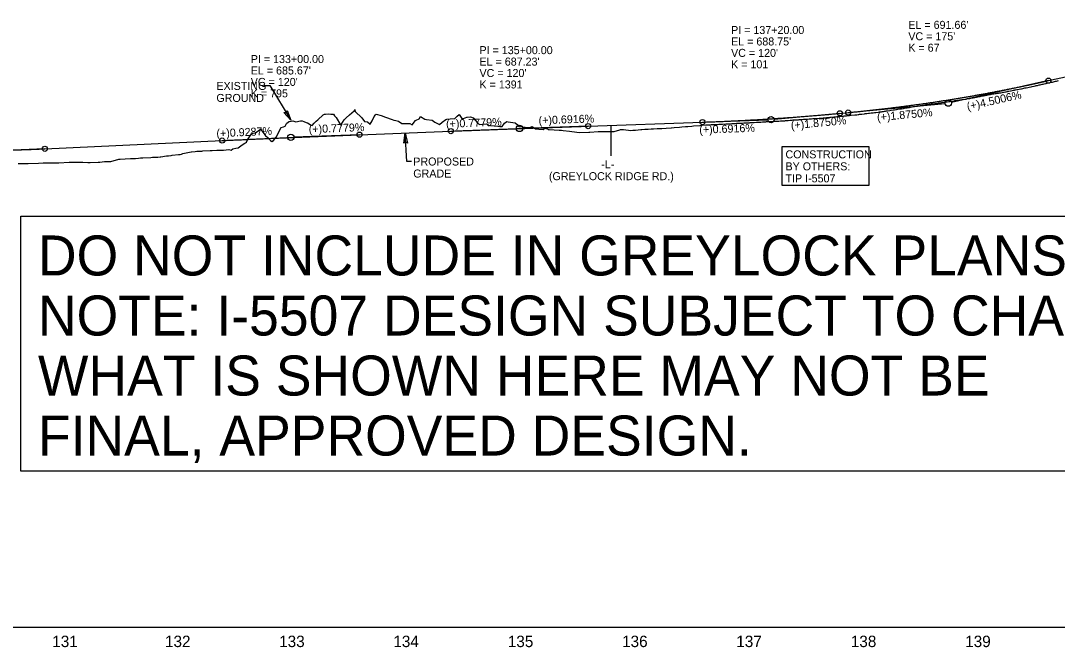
# Model space of a CAD drawing. Extents: x 1518255 to 1527303, y 471773 to 504546.
# Drawn here: x 1520134 to 1521041, y 497627 to 498175 of the extents above; entities that cross this region are included whole.
import ezdxf

# ---------------------------------------------------------------- set-up
doc = ezdxf.new("R2010")
doc.units = 0
for name, color, linetype in [('Exist Profile Cell', 7, 'Continuous'), ('Exist Vertical Profile Ground Line', 7, 'Continuous'), ('Exist Vertical Profile Horizontal Axis Label Major', 7, 'Continuous'), ('Prop Dimension', 7, 'Continuous'), ('Prop Dimension Text', 7, 'Continuous'), ('Prop Grid Mask', 7, 'Continuous'), ('Prop Terminator CELL', 7, 'Continuous'), ('Prop Vertical Profile Curve Label', 7, 'Continuous'), ('Prop Vertical Profile Grade Label', 7, 'Continuous'), ('Prop VPI Label', 7, 'Continuous')]:
    doc.layers.add(name, color=color, linetype=linetype)

msp = doc.modelspace()

# ---------------------------------------------------------------- linework, layer by layer
at = {"layer": 'Exist Profile Cell'}
msp.add_line((1519570.42, 497645.02), (1521670.42, 497645.02), dxfattribs=at)
at = {"layer": 'Exist Vertical Profile Ground Line'}
msp.add_lwpolyline([(1520131.92, 498050.38), (1520136.35, 498050.4), (1520140.85, 498050.54), (1520149.78, 498050.84), (1520154, 498050.98), (1520158.71, 498050.99), (1520166.47, 498051.02), (1520167.63, 498051.09), (1520176.56, 498051.57), (1520177.57, 498051.63), (1520185.49, 498051.74), (1520188.53, 498051.78), (1520193, 498051.39), (1520194.42, 498051.37), (1520195.1, 498051.37), (1520201.99, 498051.67), (1520203.35, 498051.8), (1520207.39, 498052.19), (1520209.6, 498052.23), (1520212.28, 498052.18), (1520213.14, 498052.16), (1520220.06, 498054.32), (1520221.21, 498054.39), (1520225.58, 498054.66), (1520230.14, 498054.82), (1520234.76, 498054.97), (1520237.26, 498055.15), (1520239.07, 498055.34), (1520241.09, 498055.57), (1520248, 498055.87), (1520249.39, 498055.95), (1520251.87, 498056.06), (1520254.14, 498056.02), (1520256.24, 498056.36), (1520256.92, 498056.45), (1520261.76, 498057.08), (1520263.47, 498057.3), (1520265.85, 498057.62), (1520266.78, 498057.75), (1520272.34, 498058.36), (1520273.79, 498058.36), (1520274.78, 498058.78), (1520276.1, 498059.35), (1520283.32, 498060.75), (1520283.71, 498060.78), (1520286.76, 498061.01), (1520288.2, 498061.35), (1520292.64, 498061.44), (1520293.38, 498061.46), (1520299.89, 498061.77), (1520301.57, 498061.88), (1520305.78, 498062.18), (1520310.5, 498062.25), (1520311.59, 498062.27), (1520316.16, 498062.67), (1520318.25, 498062.24), (1520319.68, 498063.48), (1520322.34, 498063.85), (1520324.53, 498064.18), (1520328.02, 498066.96), (1520328.36, 498067.19), (1520329.72, 498068.1), (1520330.94, 498068.71), (1520331.6, 498069.28), (1520332.56, 498071.3), (1520334.88, 498074.65), (1520336.22, 498076.55), (1520337.29, 498076.95), (1520337.66, 498077.09), (1520339.48, 498077.36), (1520343.18, 498080.08), (1520343.91, 498080.51), (1520344.26, 498080.39), (1520346.21, 498077.76), (1520348.38, 498074.83), (1520350.1, 498073.41), (1520352.61, 498070.61), (1520353.95, 498069.73), (1520355.3, 498070.65), (1520357.68, 498073.64), (1520361.94, 498082.03), (1520364.07, 498082.72), (1520365.65, 498083.23), (1520366.66, 498085.4), (1520368.47, 498087.11), (1520368.88, 498087.21), (1520369.32, 498087.35), (1520372.28, 498087.85), (1520373, 498087.63), (1520374.92, 498087.04), (1520379.01, 498087.91), (1520380.32, 498087.7), (1520381.93, 498087.29), (1520383.91, 498086.46), (1520385.01, 498086.12), (1520388.33, 498083.94), (1520389.13, 498083.76), (1520390.86, 498085.7), (1520392.53, 498087.59), (1520393.94, 498088.84), (1520398.87, 498093.09), (1520399.96, 498093.69), (1520400.78, 498093.73), (1520403.82, 498093.94), (1520405.52, 498093.75), (1520407.72, 498093.72), (1520408.72, 498092.35), (1520409.39, 498091.42), (1520410.21, 498090.9), (1520413.94, 498084.35), (1520414.33, 498084.1), (1520417.18, 498088.8), (1520417.65, 498089.26), (1520418.9, 498090.51), (1520421.72, 498093.22), (1520425.74, 498096.6), (1520426.29, 498097.61), (1520426.68, 498095.96), (1520432.64, 498090.53), (1520434.98, 498087.26), (1520435.5, 498087.2), (1520437.41, 498086.97), (1520439.91, 498084.92), (1520441.55, 498087.83), (1520443.34, 498091.66), (1520444.43, 498092.95), (1520444.96, 498093.57), (1520449.36, 498092.47), (1520453.36, 498091.07), (1520459.22, 498089), (1520460.65, 498088.34), (1520462.29, 498087.99), (1520464.48, 498087.52), (1520467.67, 498085.44), (1520469.07, 498085.45), (1520471.22, 498085.45), (1520474.4, 498085.44), (1520476.63, 498084.32), (1520479.55, 498088.1), (1520480.15, 498088.38), (1520482.67, 498089.54), (1520483.76, 498091.75), (1520487.61, 498089.26), (1520489.22, 498089), (1520494.04, 498088.31), (1520496.49, 498086.72), (1520498.01, 498085.87), (1520500.35, 498084.57), (1520502.82, 498086.76), (1520506.07, 498089.15), (1520506.94, 498089.26), (1520509.81, 498089.6), (1520513.99, 498089.95), (1520515.86, 498091.78), (1520517.61, 498093.47), (1520519.88, 498089.93), (1520521.53, 498089.9), (1520524.27, 498091.12), (1520524.79, 498091.16), (1520527.58, 498091.34), (1520529.95, 498090.46), (1520533.72, 498086.17), (1520534.48, 498085.31), (1520535.11, 498085.06), (1520535.42, 498084.57), (1520541.61, 498085.29), (1520542.65, 498084.53), (1520543.41, 498083.97), (1520544.95, 498083.88), (1520551.58, 498083.09), (1520553.29, 498082.88), (1520555.17, 498082.83), (1520557.36, 498085.67), (1520559.34, 498087.25), (1520560.51, 498087.08), (1520566.68, 498086.11), (1520568.47, 498084.68), (1520569.71, 498082.76), (1520578.37, 498082.05), (1520579.76, 498081.93), (1520580.68, 498082.56), (1520581.57, 498082.8), (1520584.45, 498080.75), (1520587.3, 498080.57), (1520591.09, 498080.31), (1520592.8, 498081.58), (1520593.87, 498081.23), (1520594.5, 498081.07), (1520595.49, 498080.26), (1520596.23, 498080.21), (1520605.15, 498079.68), (1520607.16, 498079.55), (1520608.62, 498079.47), (1520614.08, 498078.84), (1520620.46, 498078.01), (1520622.81, 498077.62), (1520631.13, 498077.99), (1520631.94, 498078.04), (1520639.24, 498078.52), (1520640.87, 498078.62), (1520641.19, 498078.64), (1520646.97, 498078.41), (1520649.8, 498078.39), (1520651.29, 498078.38), (1520653.29, 498078.53), (1520658.28, 498080.11), (1520658.73, 498080.14), (1520661.37, 498080.29), (1520667.68, 498079.44), (1520669.56, 498079.57), (1520671.72, 498079.71), (1520676.59, 498080.17), (1520677.32, 498080.24), (1520679.93, 498080.41), (1520682.94, 498080.61), (1520685.52, 498080.73), (1520687.55, 498080.82), (1520690.86, 498081.07), (1520694.44, 498081.15), (1520694.81, 498081.16), (1520698.61, 498081.47), (1520702.92, 498081.83), (1520703.37, 498081.85), (1520705.74, 498081.97), (1520710.35, 498082.36), (1520712.3, 498082.52), (1520715.46, 498082.78), (1520717.51, 498082.96), (1520721.23, 498083.26), (1520722.69, 498083.37), (1520728.09, 498083.81), (1520728.57, 498083.83), (1520730.16, 498083.97), (1520733.25, 498084.25), (1520736.75, 498084.41), (1520738.03, 498084.49), (1520738.35, 498084.51), (1520742.17, 498084.68), (1520743.63, 498084.75), (1520744.7, 498084.85), (1520745.9, 498084.9), (1520746.29, 498084.92), (1520747.79, 498085), (1520750.79, 498085.19), (1520751.77, 498085.23), (1520752.4, 498085.24), (1520752.84, 498085.26), (1520753.78, 498085.32), (1520756.04, 498085.45), (1520757.78, 498085.52), (1520758.91, 498085.61), (1520760.15, 498085.67), (1520761.33, 498085.7), (1520761.65, 498085.72), (1520762.15, 498085.75), (1520764.37, 498085.88), (1520764.9, 498085.91), (1520765.29, 498085.92), (1520766.73, 498085.96), (1520768.66, 498086.1), (1520769.52, 498086.14), (1520771.41, 498086.21), (1520772.07, 498086.24), (1520772.92, 498086.31), (1520773.86, 498086.37), (1520774.53, 498086.38), (1520775.66, 498086.39), (1520777.62, 498086.53), (1520778.65, 498086.59), (1520780.68, 498086.7), (1520781.02, 498086.71), (1520781.48, 498086.76), (1520782.81, 498086.88), (1520783.76, 498086.9), (1520784.6, 498086.92), (1520785.26, 498086.99), (1520785.75, 498087.04), (1520786.4, 498087.12), (1520786.86, 498087.12), (1520790.03, 498087.27), (1520793.14, 498087.46), (1520793.56, 498087.46), (1520794.35, 498087.53), (1520795.34, 498087.63), (1520796.07, 498087.63), (1520797.15, 498087.67), (1520798.63, 498087.74), (1520799.16, 498087.78), (1520800.49, 498087.84), (1520801.01, 498087.88), (1520802.52, 498087.95), (1520802.92, 498088), (1520805.29, 498088.23), (1520807.23, 498088.34), (1520807.89, 498088.39), (1520808.36, 498088.43), (1520808.88, 498088.49), (1520809.68, 498088.59), (1520811.53, 498088.61), (1520813.28, 498088.8), (1520814.53, 498088.85), (1520815.08, 498088.88), (1520815.84, 498088.91), (1520816.75, 498088.99), (1520817.57, 498089.06), (1520818.65, 498089.2), (1520820.64, 498089.23), (1520822.23, 498089.43), (1520823.71, 498089.52), (1520824.03, 498089.54), (1520824.63, 498089.57), (1520825.83, 498089.65), (1520826.8, 498089.77), (1520827.63, 498089.88), (1520828.79, 498089.91), (1520829.87, 498089.98), (1520832.5, 498090.16), (1520833.1, 498090.21), (1520834.78, 498090.29), (1520835.97, 498090.42), (1520836.58, 498090.49), (1520837.44, 498090.53), (1520838.39, 498090.56), (1520839.07, 498090.66), (1520840.37, 498090.78), (1520841.74, 498090.92), (1520842.1, 498090.95), (1520842.96, 498091.04), (1520845.15, 498091.24), (1520845.53, 498091.3), (1520846.08, 498091.32), (1520847.34, 498091.34), (1520848.24, 498091.5), (1520849.15, 498091.62), (1520850.42, 498091.74), (1520851.3, 498091.8), (1520853.36, 498092.03), (1520854.33, 498092.12), (1520854.75, 498092.16), (1520856.3, 498092.24), (1520857.4, 498092.4), (1520858.1, 498092.47), (1520859.1, 498092.6), (1520859.91, 498092.66), (1520860.48, 498092.73), (1520863.5, 498093.06), (1520863.99, 498093.09), (1520865.27, 498093.17), (1520866.57, 498093.37), (1520867.08, 498093.43), (1520867.8, 498093.53), (1520868.88, 498093.61), (1520869.64, 498093.71), (1520872.13, 498094.05), (1520872.69, 498094.12), (1520874.25, 498094.22), (1520875.72, 498094.49), (1520876.04, 498094.53), (1520876.5, 498094.6), (1520877.85, 498094.75), (1520878.82, 498094.86), (1520879.73, 498094.92), (1520880.83, 498095.12), (1520881.88, 498095.25), (1520884.21, 498095.53), (1520885.2, 498095.65), (1520886.83, 498095.84), (1520887.6, 498095.93), (1520887.96, 498095.98), (1520888.62, 498096.02), (1520889.56, 498096.23), (1520890.4, 498096.39), (1520890.99, 498096.45), (1520892.2, 498096.58), (1520894.34, 498096.92), (1520895.47, 498097.09), (1520897.08, 498097.34), (1520898.29, 498097.55), (1520899.38, 498097.76), (1520900.14, 498097.84), (1520901.2, 498097.96), (1520902.7, 498098.22), (1520903.35, 498098.32), (1520904.4, 498098.48), (1520906.23, 498098.77), (1520906.56, 498098.81), (1520907.06, 498098.9), (1520908.38, 498099.16), (1520909.29, 498099.25), (1520911.41, 498099.59), (1520911.93, 498099.69), (1520912.3, 498099.74), (1520913.75, 498099.97), (1520915.84, 498100.28), (1520918.41, 498100.72), (1520919.09, 498100.83), (1520920.2, 498101), (1520920.95, 498101.14), (1520921.46, 498101.22), (1520922.75, 498101.45), (1520924.6, 498101.67), (1520926.32, 498102.03), (1520926.96, 498102.1), (1520927.53, 498102.16), (1520928.12, 498102.24), (1520928.99, 498102.36), (1520929.93, 498102.51), (1520930.58, 498102.6), (1520931.74, 498102.77), (1520933.62, 498102.96), (1520934.13, 498103.03), (1520934.83, 498103.13), (1520936.64, 498103.4), (1520937.11, 498103.46), (1520937.79, 498103.55), (1520938.92, 498103.72), (1520939.7, 498103.83), (1520942.17, 498104.13), (1520942.71, 498104.21), (1520944.3, 498104.51), (1520945.76, 498104.68), (1520946.11, 498104.73), (1520946.61, 498104.8), (1520948.78, 498105.16), (1520950.58, 498105.43), (1520951.02, 498105.5), (1520951.8, 498105.63), (1520953.28, 498105.94), (1520955.09, 498106.21), (1520955.43, 498106.23), (1520957.11, 498106.46), (1520957.89, 498106.46), (1520958.45, 498106.52), (1520959.83, 498106.68), (1520960.38, 498106.76), (1520960.9, 498106.88), (1520962.27, 498107.23), (1520964.25, 498107.5), (1520966.32, 498107.92), (1520966.98, 498108.05), (1520968.7, 498108.35), (1520970.01, 498108.61), (1520971.29, 498108.92), (1520973.13, 498109.17), (1520974.19, 498109.41), (1520975.14, 498109.62), (1520976.06, 498109.78), (1520976.66, 498109.93), (1520977.55, 498110.04), (1520978.32, 498110.2), (1520979.11, 498110.34), (1520980.28, 498110.64), (1520982.15, 498110.92), (1520984.07, 498111.46), (1520985.12, 498111.58), (1520986.44, 498111.75), (1520987.22, 498111.81), (1520988.16, 498111.96), (1520989.27, 498112.15), (1520989.94, 498112.24), (1520991.38, 498112.45), (1520993.59, 498112.89), (1520994.18, 498113.03), (1520995.33, 498113.23), (1520995.95, 498113.32), (1520996.91, 498113.51), (1520997.24, 498113.56), (1520997.81, 498113.69), (1520998.27, 498113.79), (1520999.79, 498114.04), (1521000.09, 498114.1), (1521000.46, 498114.17), (1521002.28, 498114.53), (1521003.28, 498114.76), (1521003.65, 498114.86), (1521004.21, 498114.94), (1521005.3, 498115.12), (1521005.68, 498115.19), (1521006.31, 498115.3), (1521007.27, 498115.53), (1521008.83, 498115.83), (1521009.31, 498115.93), (1521010.49, 498116.17), (1521012.34, 498116.56), (1521012.65, 498116.65), (1521013.12, 498116.73), (1521013.55, 498116.81), (1521014.85, 498117.06), (1521016.15, 498117.33), (1521017.97, 498117.72), (1521018.64, 498117.87), (1521020.08, 498118.17), (1521020.45, 498118.24), (1521021.65, 498118.53), (1521022.07, 498118.6), (1521023.36, 498118.87), (1521024.76, 498119.19), (1521025.63, 498119.41), (1521026.63, 498119.62), (1521027.45, 498119.8), (1521028.43, 498120), (1521029.3, 498120.19), (1521030.39, 498120.44), (1521031.05, 498120.59), (1521032.92, 498121.01), (1521033.72, 498121.19), (1521034.47, 498121.38), (1521035.49, 498121.59), (1521036.45, 498121.8), (1521037.25, 498121.97), (1521039.08, 498122.39), (1521039.44, 498122.46), (1521040, 498122.58), (1521041.81, 498123)], dxfattribs=at)
at = {"layer": 'Prop Dimension'}
for p, q in [((1520347.27, 498118.69), (1520352.21, 498118.69)), ((1520352.21, 498118.69), (1520370.42, 498088.28)), ((1520471.87, 498052.15), (1520470.42, 498077.27)), ((1520476.04, 498052.15), (1520471.87, 498052.15))]:
    msp.add_line(p, q, dxfattribs=at)
at = {"layer": 'Prop Grid Mask'}
for p, q in [((1521032.92, 498122.99), (1521065.42, 498130.3)), ((1520850.42, 498094.39), (1520857.92, 498095.09)), ((1520630.42, 498083.23), (1520730.42, 498086.69)), ((1520430.42, 498075.71), (1520510.42, 498078.82)), ((1520155.42, 498063.4), (1520310.42, 498070.59))]:
    msp.add_line(p, q, dxfattribs=at)
for points in [[(1520800, 498065.41), (1520875.98, 498065.41), (1520875.98, 498031.27), (1520800, 498031.27)], [(1520134.29, 498004.57), (1521246.11, 498004.57), (1521246.11, 497781.32), (1520134.29, 497781.32)]]:
    msp.add_lwpolyline(points, close=True, dxfattribs=at)
for points in [[(1520857.92, 498095.09), (1520861.42, 498095.43), (1520864.92, 498095.77), (1520868.42, 498096.12), (1520871.92, 498096.48), (1520875.42, 498096.85), (1520878.92, 498097.23), (1520882.42, 498097.62), (1520885.92, 498098.01), (1520889.42, 498098.42), (1520892.92, 498098.83), (1520896.42, 498099.26), (1520899.92, 498099.69), (1520903.42, 498100.14), (1520906.92, 498100.59), (1520910.42, 498101.05), (1520913.92, 498101.52), (1520917.42, 498102), (1520920.92, 498102.49), (1520924.42, 498102.99), (1520927.92, 498103.49), (1520931.42, 498104.01), (1520934.92, 498104.54), (1520938.42, 498105.07), (1520941.92, 498105.62), (1520945.42, 498106.17), (1520948.92, 498106.73), (1520952.42, 498107.3), (1520955.92, 498107.88), (1520959.42, 498108.47), (1520962.92, 498109.07), (1520966.42, 498109.68), (1520969.92, 498110.3), (1520973.42, 498110.93), (1520976.92, 498111.56), (1520980.42, 498112.21), (1520983.92, 498112.86), (1520987.42, 498113.52), (1520990.92, 498114.2), (1520994.42, 498114.88), (1520997.92, 498115.57), (1521001.42, 498116.27), (1521004.92, 498116.98), (1521008.42, 498117.7), (1521011.92, 498118.43), (1521015.42, 498119.16), (1521018.92, 498119.91), (1521022.42, 498120.67), (1521025.92, 498121.43), (1521029.42, 498122.2), (1521032.92, 498122.99)], [(1520730.42, 498086.69), (1520732.82, 498086.78), (1520735.22, 498086.86), (1520737.62, 498086.95), (1520740.02, 498087.05), (1520742.42, 498087.14), (1520744.82, 498087.24), (1520747.22, 498087.34), (1520749.62, 498087.45), (1520752.02, 498087.55), (1520754.42, 498087.66), (1520756.82, 498087.78), (1520759.22, 498087.89), (1520761.62, 498088.01), (1520764.02, 498088.13), (1520766.42, 498088.26), (1520768.82, 498088.38), (1520771.22, 498088.51), (1520773.62, 498088.65), (1520776.02, 498088.78), (1520778.42, 498088.92), (1520780.82, 498089.06), (1520783.22, 498089.2), (1520785.62, 498089.35), (1520788.02, 498089.5), (1520790.42, 498089.65), (1520792.82, 498089.81), (1520795.22, 498089.97), (1520797.62, 498090.13), (1520800.02, 498090.29), (1520802.42, 498090.46), (1520804.82, 498090.63), (1520807.22, 498090.8), (1520809.62, 498090.98), (1520812.02, 498091.15), (1520814.42, 498091.34), (1520816.82, 498091.52), (1520819.22, 498091.71), (1520821.62, 498091.9), (1520824.02, 498092.09), (1520826.42, 498092.28), (1520828.82, 498092.48), (1520831.22, 498092.68), (1520833.62, 498092.89), (1520836.02, 498093.09), (1520838.42, 498093.3), (1520840.82, 498093.51), (1520843.22, 498093.73), (1520845.62, 498093.95), (1520848.02, 498094.17), (1520850.42, 498094.39)], [(1520510.42, 498078.82), (1520512.82, 498078.92), (1520515.22, 498079.01), (1520517.62, 498079.1), (1520520.02, 498079.2), (1520522.42, 498079.29), (1520524.82, 498079.38), (1520527.22, 498079.47), (1520529.62, 498079.56), (1520532.02, 498079.66), (1520534.42, 498079.75), (1520536.82, 498079.84), (1520539.22, 498079.93), (1520541.62, 498080.02), (1520544.02, 498080.11), (1520546.42, 498080.2), (1520548.82, 498080.29), (1520551.22, 498080.38), (1520553.62, 498080.47), (1520556.02, 498080.56), (1520558.42, 498080.65), (1520560.82, 498080.74), (1520563.22, 498080.83), (1520565.62, 498080.92), (1520568.02, 498081.01), (1520570.42, 498081.09), (1520572.82, 498081.18), (1520575.22, 498081.27), (1520577.62, 498081.36), (1520580.02, 498081.44), (1520582.42, 498081.53), (1520584.82, 498081.62), (1520587.22, 498081.71), (1520589.62, 498081.79), (1520592.02, 498081.88), (1520594.42, 498081.96), (1520596.82, 498082.05), (1520599.22, 498082.14), (1520601.62, 498082.22), (1520604.02, 498082.31), (1520606.42, 498082.39), (1520608.82, 498082.48), (1520611.22, 498082.56), (1520613.62, 498082.65), (1520616.02, 498082.73), (1520618.42, 498082.82), (1520620.82, 498082.9), (1520623.22, 498082.98), (1520625.62, 498083.07), (1520628.02, 498083.15), (1520630.42, 498083.23)], [(1520310.42, 498070.59), (1520312.82, 498070.7), (1520315.22, 498070.82), (1520317.62, 498070.93), (1520320.02, 498071.04), (1520322.42, 498071.15), (1520324.82, 498071.26), (1520327.22, 498071.36), (1520329.62, 498071.47), (1520332.02, 498071.58), (1520334.42, 498071.69), (1520336.82, 498071.8), (1520339.22, 498071.9), (1520341.62, 498072.01), (1520344.02, 498072.12), (1520346.42, 498072.22), (1520348.82, 498072.33), (1520351.22, 498072.44), (1520353.62, 498072.54), (1520356.02, 498072.65), (1520358.42, 498072.75), (1520360.82, 498072.85), (1520363.22, 498072.96), (1520365.62, 498073.06), (1520368.02, 498073.16), (1520370.42, 498073.27), (1520372.82, 498073.37), (1520375.22, 498073.47), (1520377.62, 498073.57), (1520380.02, 498073.67), (1520382.42, 498073.77), (1520384.82, 498073.87), (1520387.22, 498073.97), (1520389.62, 498074.07), (1520392.02, 498074.17), (1520394.42, 498074.27), (1520396.82, 498074.37), (1520399.22, 498074.47), (1520401.62, 498074.57), (1520404.02, 498074.66), (1520406.42, 498074.76), (1520408.82, 498074.86), (1520411.22, 498074.95), (1520413.62, 498075.05), (1520416.02, 498075.15), (1520418.42, 498075.24), (1520420.82, 498075.34), (1520423.22, 498075.43), (1520425.62, 498075.53), (1520428.02, 498075.62), (1520430.42, 498075.71)], [(1519985.42, 498066.64), (1519988.82, 498066.35), (1519992.22, 498066.08), (1519995.62, 498065.81), (1519999.02, 498065.56), (1520002.42, 498065.31), (1520005.82, 498065.07), (1520009.22, 498064.84), (1520012.62, 498064.62), (1520016.02, 498064.41), (1520019.42, 498064.21), (1520022.82, 498064.01), (1520026.22, 498063.83), (1520029.62, 498063.65), (1520033.02, 498063.48), (1520036.42, 498063.33), (1520039.82, 498063.18), (1520043.22, 498063.04), (1520046.62, 498062.9), (1520050.02, 498062.78), (1520053.42, 498062.67), (1520056.82, 498062.56), (1520060.22, 498062.47), (1520063.62, 498062.38), (1520067.02, 498062.3), (1520070.42, 498062.23), (1520073.82, 498062.17), (1520077.22, 498062.12), (1520080.62, 498062.08), (1520084.02, 498062.04), (1520087.42, 498062.02), (1520090.82, 498062), (1520094.22, 498062), (1520097.62, 498062), (1520101.02, 498062.01), (1520104.42, 498062.03), (1520107.82, 498062.06), (1520111.22, 498062.1), (1520114.62, 498062.14), (1520118.02, 498062.2), (1520121.42, 498062.26), (1520124.82, 498062.34), (1520128.22, 498062.42), (1520131.62, 498062.51), (1520135.02, 498062.61), (1520138.42, 498062.72), (1520141.82, 498062.84), (1520145.22, 498062.96), (1520148.62, 498063.1), (1520152.02, 498063.24), (1520155.42, 498063.4)]]:
    msp.add_spline(points, degree=3, dxfattribs=at)
at = {"layer": 'Prop Terminator CELL'}
for points in [[(1520367.12, 498096.8), (1520370.42, 498088.28), (1520364.39, 498095.23), (1520366.36, 498095.06)], [(1520469.39, 498068.19), (1520470.42, 498077.27), (1520472.54, 498068.33), (1520470.87, 498069.38)]]:
    msp.add_lwpolyline(points, close=True, dxfattribs=at)
at = {"layer": 'Prop Vertical Profile Curve Label'}
msp.add_line((1520650.54, 498057.28), (1520650.54, 498083.93), dxfattribs=at)
for centre in [(1521032.92, 498122.99), (1520850.42, 498094.39), (1520857.92, 498095.09), (1520630.42, 498083.23), (1520730.42, 498086.69), (1520310.42, 498070.59), (1520430.42, 498075.71), (1520510.42, 498078.82), (1520155.42, 498063.4)]:
    msp.add_circle(centre, 2.25, dxfattribs=at)
at = {"layer": 'Prop VPI Label'}
for p, q in [((1521032.92, 498122.99), (1520948.1, 498103.9)), ((1520857.92, 498095.09), (1520942.68, 498103.04)), ((1520850.42, 498094.39), (1520793.15, 498089.02)), ((1520630.42, 498083.23), (1520573.16, 498081.25)), ((1520730.42, 498086.69), (1520787.67, 498088.67)), ((1520310.42, 498070.59), (1520367.67, 498073.25)), ((1520430.42, 498075.71), (1520373.16, 498073.49)), ((1520510.42, 498078.82), (1520567.67, 498081.05)), ((1520155.42, 498063.4), (1520073.16, 498059.58))]:
    msp.add_line(p, q, dxfattribs=at)
for centre in [(1520945.42, 498103.3), (1520790.42, 498088.77), (1520570.42, 498081.16), (1520370.42, 498073.38)]:
    msp.add_circle(centre, 2.75, dxfattribs=at)

# ---------------------------------------------------------------- texts
at = {"layer": 'Exist Vertical Profile Horizontal Axis Label Major'}
for s, p in [('131', (1520161.88, 497627.52)), ('132', (1520260.43, 497627.52)), ('133', (1520360.27, 497627.52)), ('134', (1520460.11, 497627.52)), ('135', (1520560.2, 497627.52)), ('136', (1520660.14, 497627.52)), ('137', (1520760, 497627.52)), ('138', (1520860.13, 497627.52)), ('139', (1520960.17, 497627.52))]:
    msp.add_text(s, height=10, dxfattribs=at).set_placement(p)
at = {"layer": 'Prop Dimension Text'}
for s, p in [('EXISTING', (1520305.38, 498114.86)), ('GROUND', (1520305.38, 498104.36)), ('PROPOSED', (1520477.53, 498048.75)), ('GRADE', (1520477.53, 498038.25))]:
    msp.add_text(s, height=7, dxfattribs=at).set_placement(p)
at = {"layer": 'Prop Vertical Profile Curve Label'}
for s, p in [("VC = 175'", (1520910.42, 498158.3)), ('K = 67', (1520910.42, 498148.3)), ("VC = 120'", (1520755.42, 498143.77)), ('K = 101', (1520755.42, 498133.77)), ("VC = 120'", (1520535.42, 498126.16)), ("VC = 120'", (1520335.42, 498118.38)), ('K = 1391', (1520535.42, 498116.16)), ('K = 795', (1520335.42, 498108.38))]:
    msp.add_text(s, height=7, dxfattribs=at).set_placement(p)
at = {"layer": 'Prop Vertical Profile Grade Label'}
for s, rotation, p in [('(+)4.5006%', 12.682, (1520962.39, 498096.87)), ('(+)0.7779%', 2.22735, (1520506.32, 498081.67)), ('(+)0.6916%', 1.9805, (1520587.21, 498084.74)), ('(+)1.8750%', 5.35578, (1520808.02, 498080.37)), ('(+)1.8750%', 5.35578, (1520883.37, 498087.44)), ('(+)0.9287%', 2.65872, (1520305.55, 498073.37)), ('(+)0.7779%', 2.22735, (1520386.26, 498077)), ('(+)0.6916%', 1.9805, (1520727.71, 498076.59))]:
    msp.add_text(s, height=7, rotation=rotation, dxfattribs=at).set_placement(p)
at = {"layer": 'Prop VPI Label'}
for s, height, p in [("EL = 691.66'", 7, (1520910.42, 498168.3)), ('PI = 137+20.00', 7, (1520755.42, 498163.77)), ("EL = 688.75'", 7, (1520755.42, 498153.77)), ('PI = 133+00.00', 7, (1520335.42, 498138.38)), ('PI = 135+00.00', 7, (1520535.42, 498146.16)), ("EL = 687.23'", 7, (1520535.42, 498136.16)), ("EL = 685.67'", 7, (1520335.42, 498128.38)), ('CONSTRUCTION', 7, (1520803, 498055.02)), ('-L-', 7, (1520641.9, 498046.43)), ('BY OTHERS:', 7, (1520803, 498044.52)), ('(GREYLOCK RIDGE RD.)', 7, (1520596.14, 498035.93)), ('TIP I-5507', 7, (1520803, 498034.02)), ('DO NOT INCLUDE IN GREYLOCK PLANS', 35, (1520149.32, 497952.56)), ('NOTE: I-5507 DESIGN SUBJECT TO CHANGE,', 35, (1520149.32, 497900.06)), ('WHAT IS SHOWN HERE MAY NOT BE', 35, (1520149.32, 497847.56)), ('FINAL, APPROVED DESIGN.', 35, (1520149.32, 497795.06))]:
    msp.add_text(s, height=height, dxfattribs=at).set_placement(p)

doc.saveas('drawing.dxf')
